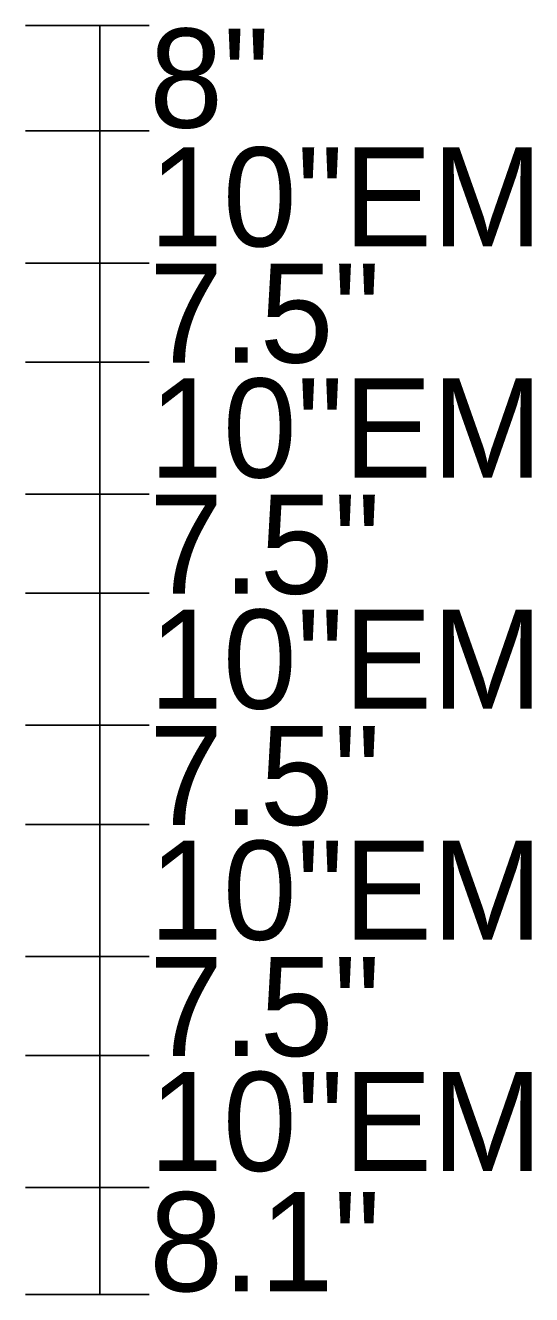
# Model space of a CAD drawing. Extents: x 1806251 to 1809821, y 414895 to 422886.
# Drawn here: x 1809677.952 to 1809678.335, y 414961.9 to 414962.861 of the extents above; entities that cross this region are included whole.
import ezdxf

# ---------------------------------------------------------------- set-up
doc = ezdxf.new("R2010")
doc.units = 0
doc.layers.add('GSDIMS', color=7, linetype='Continuous')

msp = doc.modelspace()

# ---------------------------------------------------------------- linework, layer by layer
at = {"layer": 'GSDIMS'}
for p, q in [((1809677.95225, 414962.861), (1809678.046, 414962.861)), ((1809678.0085, 414962.78107), (1809678.0085, 414962.861)), ((1809677.95225, 414962.78107), (1809678.046, 414962.78107)), ((1809677.95225, 414962.78107), (1809678.046, 414962.78107)), ((1809678.0085, 414962.78107), (1809678.0085, 414962.68107)), ((1809677.95225, 414962.68107), (1809678.046, 414962.68107)), ((1809677.95225, 414962.68107), (1809678.046, 414962.68107)), ((1809678.0085, 414962.60607), (1809678.0085, 414962.68107)), ((1809677.95225, 414962.60607), (1809678.046, 414962.60607)), ((1809677.95225, 414962.60607), (1809678.046, 414962.60607)), ((1809678.0085, 414962.60607), (1809678.0085, 414962.50607)), ((1809677.95225, 414962.50607), (1809678.046, 414962.50607)), ((1809677.95225, 414962.50607), (1809678.046, 414962.50607)), ((1809678.0085, 414962.43107), (1809678.0085, 414962.50607)), ((1809677.95225, 414962.43107), (1809678.046, 414962.43107)), ((1809677.95225, 414962.43107), (1809678.046, 414962.43107)), ((1809678.0085, 414962.43107), (1809678.0085, 414962.33107)), ((1809677.95225, 414962.33107), (1809678.046, 414962.33107)), ((1809677.95225, 414962.33107), (1809678.046, 414962.33107)), ((1809678.0085, 414962.25607), (1809678.0085, 414962.33107)), ((1809677.95225, 414962.25607), (1809678.046, 414962.25607)), ((1809677.95225, 414962.25607), (1809678.046, 414962.25607)), ((1809678.0085, 414962.25607), (1809678.0085, 414962.15607)), ((1809677.95225, 414962.15607), (1809678.046, 414962.15607)), ((1809677.95225, 414962.15607), (1809678.046, 414962.15607)), ((1809678.0085, 414962.08107), (1809678.0085, 414962.15607)), ((1809677.95225, 414962.08107), (1809678.046, 414962.08107)), ((1809677.95225, 414962.08107), (1809678.046, 414962.08107)), ((1809678.0085, 414962.08107), (1809678.0085, 414961.98107)), ((1809677.95225, 414961.98107), (1809678.046, 414961.98107)), ((1809677.95225, 414961.98107), (1809678.046, 414961.98107)), ((1809678.0085, 414961.9), (1809678.0085, 414961.98107)), ((1809677.95225, 414961.9), (1809678.046, 414961.9))]:
    msp.add_line(p, q, dxfattribs=at)

# ---------------------------------------------------------------- texts
for s, p in [('8"', (1809678.046, 414962.78357)), ('10"EM', (1809678.046, 414962.69365)), ('7.5"', (1809678.046, 414962.60565)), ('10"EM', (1809678.046, 414962.51865)), ('7.5"', (1809678.046, 414962.43065)), ('10"EM', (1809678.046, 414962.34365)), ('7.5"', (1809678.046, 414962.25565)), ('10"EM', (1809678.046, 414962.16865)), ('7.5"', (1809678.046, 414962.08065)), ('10"EM', (1809678.046, 414961.99365)), ('8.1"', (1809678.046, 414961.90257))]:
    msp.add_text(s, height=0.075, dxfattribs=at).set_placement(p)

doc.saveas('drawing.dxf')
